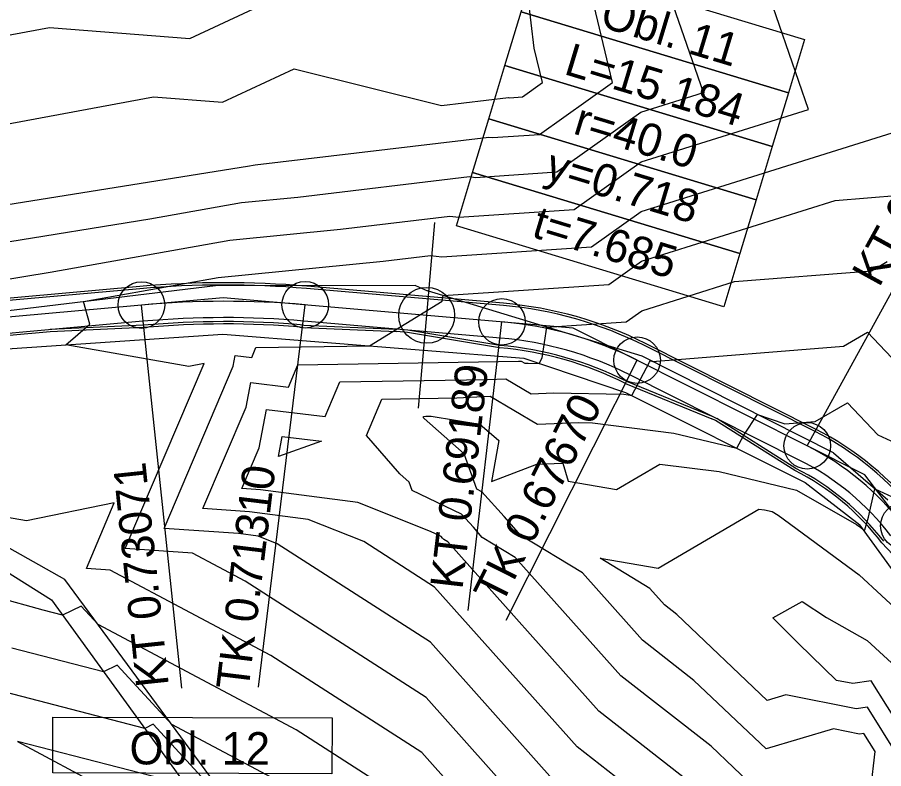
# Model space of a CAD drawing. Extents: x -549394 to -546608, y -1037055 to -1033629.
# Drawn here: x -548286 to -548193, y -1035592.8 to -1035512.1 of the extents above; entities that cross this region are included whole.
import ezdxf

# ---------------------------------------------------------------- set-up
doc = ezdxf.new("R2010")
doc.units = 0
for name, color, linetype in [('hlavni_vrst', 7, 'Continuous'), ('hrana_L', 7, 'Continuous'), ('norm_vrst', 7, 'Continuous'), ('POLYGONY_SITUACE_PO', 7, 'Continuous'), ('u_sirka_1_0m', 7, 'Continuous'), ('x_navrh_C11', 7, 'Continuous'), ('x_osa_C11', 7, 'Continuous'), ('x_popis_oblouky_C11', 7, 'Continuous'), ('x_popis_pricne_rezy_C11', 7, 'Continuous')]:
    doc.layers.add(name, color=color, linetype=linetype)

msp = doc.modelspace()

# ---------------------------------------------------------------- linework, layer by layer
at = {"layer": 'hlavni_vrst'}
for p, q in [((-548212.331, -1035520.205), (-548218.723, -1035501.7)), ((-548219.074, -1035522.316), (-548212.331, -1035520.205)), ((-548228.079, -1035528.712), (-548219.074, -1035522.316)), ((-548236.814, -1035529.301), (-548228.079, -1035528.712)), ((-548255.908, -1035531.413), (-548237.487, -1035529.22)), ((-548237.487, -1035529.22), (-548236.814, -1035529.301)), ((-548261.972, -1035532.012), (-548255.908, -1035531.413)), ((-548271.803, -1035533.774), (-548261.972, -1035532.012)), ((-548298.044, -1035537.991), (-548271.803, -1035533.774)), ((-548197.301, -1035547.423), (-548194.73, -1035545.927)), ((-548194.73, -1035545.927), (-548186.887, -1035554.18)), ((-548217.804, -1035549.058), (-548197.301, -1035547.423)), ((-548220.033, -1035552.739), (-548218.13, -1035549.147)), ((-548218.13, -1035549.147), (-548218.021, -1035548.983)), ((-548218.021, -1035548.983), (-548217.804, -1035549.058)), ((-548252.974, -1035554.992), (-548251.403, -1035551.276)), ((-548251.403, -1035551.276), (-548235.529, -1035551.017)), ((-548235.529, -1035551.017), (-548233.588, -1035550.923)), ((-548233.588, -1035550.923), (-548230.844, -1035552.535)), ((-548230.844, -1035552.535), (-548228.46, -1035552.448)), ((-548228.46, -1035552.448), (-548220.912, -1035552.585)), ((-548220.912, -1035552.585), (-548220.417, -1035552.647)), ((-548220.417, -1035552.647), (-548220.033, -1035552.739)), ((-548260.067, -1035558.338), (-548259.276, -1035554.216)), ((-548259.276, -1035554.216), (-548252.974, -1035554.992)), ((-548261.928, -1035562.711), (-548260.067, -1035558.338)), ((-548259.924, -1035562.848), (-548261.928, -1035562.711)), ((-548249.471, -1035564.211), (-548259.924, -1035562.848)), ((-548241.665, -1035567.316), (-548249.471, -1035564.211)), ((-548240.523, -1035567.864), (-548241.665, -1035567.316)), ((-548240.366, -1035568.038), (-548240.523, -1035567.864)), ((-548240.249, -1035568.171), (-548240.366, -1035568.038)), ((-548239.817, -1035568.434), (-548240.249, -1035568.171)), ((-548223.569, -1035586.629), (-548239.817, -1035568.434)), ((-548283.285, -1035575.769), (-548289.508, -1035574.054)), ((-548279.19, -1035575.353), (-548281.189, -1035576.311)), ((-548277.366, -1035577.326), (-548279.19, -1035575.353)), ((-548281.189, -1035576.311), (-548283.285, -1035575.769)), ((-548256.095, -1035588.612), (-548277.366, -1035577.326)), ((-548209.69, -1035597.452), (-548223.569, -1035586.629)), ((-548243.032, -1035597.002), (-548256.095, -1035588.612))]:
    msp.add_line(p, q, dxfattribs=at)
at = {"layer": 'hrana_L'}
for p, q in [((-548264.75, -1035540.94), (-548291.18, -1035544.12)), ((-548243.27, -1035540.92), (-548264.75, -1035540.94)), ((-548243.27, -1035540.92), (-548241.98, -1035541.48)), ((-548218.94, -1035548.52), (-548241.98, -1035541.48)), ((-548291.26, -1035548), (-548263.97, -1035546.13)), ((-548263.97, -1035546.13), (-548231.65, -1035548.71)), ((-548198.38, -1035558.89), (-548218.94, -1035548.52)), ((-548231.65, -1035548.71), (-548220.71, -1035552.4)), ((-548220.71, -1035552.4), (-548201.42, -1035562.07)), ((-548198.38, -1035558.89), (-548192.54, -1035563.93)), ((-548201.42, -1035562.07), (-548195.55, -1035566.63)), ((-548177.72, -1035591.18), (-548195.55, -1035566.63)), ((-548280.93, -1035572.5), (-548287.66, -1035568.68)), ((-548288.7, -1035570.68), (-548282.38, -1035574.67)), ((-548244.89, -1035621.3), (-548280.93, -1035572.5)), ((-548282.38, -1035574.67), (-548265, -1035598.62))]:
    msp.add_line(p, q, dxfattribs=at)
at = {"layer": 'norm_vrst'}
for p, q in [((-548230.521, -1035515.424), (-548233.103, -1035494.044)), ((-548222.103, -1035519.122), (-548225.312, -1035505.67)), ((-548201.065, -1035522.013), (-548206.946, -1035504.991)), ((-548267.515, -1035514.384), (-548251.739, -1035507.018)), ((-548298.777, -1035516.185), (-548282.595, -1035513.201)), ((-548282.595, -1035513.201), (-548267.515, -1035514.384)), ((-548229.637, -1035519.128), (-548230.521, -1035515.424)), ((-548264.023, -1035521.244), (-548256.296, -1035517.637)), ((-548256.296, -1035517.637), (-548240.489, -1035521.597)), ((-548231.794, -1035520.66), (-548229.637, -1035519.128)), ((-548229.937, -1035524.686), (-548222.103, -1035519.122)), ((-548300.964, -1035526.115), (-548271.409, -1035520.665)), ((-548271.409, -1035520.665), (-548264.023, -1035521.244)), ((-548240.489, -1035521.597), (-548233.296, -1035520.741)), ((-548233.296, -1035520.741), (-548233.189, -1035520.754)), ((-548233.189, -1035520.754), (-548231.794, -1035520.66)), ((-548219.047, -1035527.642), (-548201.065, -1035522.013)), ((-548219.019, -1035532.968), (-548189.799, -1035523.821)), ((-548260.487, -1035527.968), (-548235.392, -1035524.98)), ((-548235.392, -1035524.98), (-548235.001, -1035525.027)), ((-548235.001, -1035525.027), (-548229.937, -1035524.686)), ((-548301.836, -1035534.605), (-548261.098, -1035528.059)), ((-548261.098, -1035528.059), (-548260.72, -1035527.991)), ((-548260.72, -1035527.991), (-548260.487, -1035527.968)), ((-548226.222, -1035532.738), (-548219.047, -1035527.642)), ((-548218.992, -1035538.294), (-548198.182, -1035531.78)), ((-548198.182, -1035531.78), (-548191.252, -1035531.227)), ((-548238.627, -1035533.574), (-548226.222, -1035532.738)), ((-548251.329, -1035534.857), (-548239.582, -1035533.459)), ((-548239.582, -1035533.459), (-548238.627, -1035533.574)), ((-548224.364, -1035536.764), (-548219.019, -1035532.968)), ((-548263.223, -1035536.034), (-548251.329, -1035534.857)), ((-548282.509, -1035539.49), (-548263.223, -1035536.034)), ((-548240.439, -1035537.848), (-548224.364, -1035536.764)), ((-548264.475, -1035540.055), (-548246.75, -1035538.302)), ((-548246.75, -1035538.302), (-548241.678, -1035537.698)), ((-548241.678, -1035537.698), (-548240.439, -1035537.848)), ((-548222.506, -1035540.79), (-548218.992, -1035538.294)), ((-548194.276, -1035539.325), (-548192.595, -1035538.347)), ((-548208.994, -1035540.499), (-548194.276, -1035539.325)), ((-548294.252, -1035541.377), (-548282.509, -1035539.49)), ((-548278.932, -1035542.646), (-548264.475, -1035540.055)), ((-548240.31, -1035541.99), (-548222.506, -1035540.79)), ((-548218.965, -1035543.62), (-548208.994, -1035540.499)), ((-548240.399, -1035542.587), (-548240.31, -1035541.99)), ((-548278.255, -1035545.075), (-548278.932, -1035542.646)), ((-548248.209, -1035547.388), (-548240.399, -1035542.587)), ((-548220.649, -1035544.816), (-548218.965, -1035543.62)), ((-548229.18, -1035545.391), (-548220.649, -1035544.816)), ((-548280.826, -1035547.285), (-548278.255, -1035545.075)), ((-548229.668, -1035548.68), (-548229.18, -1035545.391)), ((-548267.628, -1035549.612), (-548280.826, -1035547.285)), ((-548260.856, -1035548.639), (-548260.412, -1035547.587)), ((-548260.412, -1035547.587), (-548248.209, -1035547.388)), ((-548262.865, -1035549.587), (-548262.641, -1035548.42)), ((-548262.641, -1035548.42), (-548260.856, -1035548.639)), ((-548274.457, -1035569.165), (-548265.994, -1035549.276)), ((-548270.281, -1035567.014), (-548262.865, -1035549.587)), ((-548265.994, -1035549.276), (-548267.628, -1035549.612)), ((-548256.915, -1035551.816), (-548255.908, -1035549.431)), ((-548255.908, -1035549.431), (-548232.214, -1035549.045)), ((-548232.214, -1035549.045), (-548231.932, -1035549.031)), ((-548231.932, -1035549.031), (-548231.533, -1035549.266)), ((-548231.533, -1035549.266), (-548231.187, -1035549.253)), ((-548231.187, -1035549.253), (-548229.975, -1035549.275)), ((-548229.975, -1035549.275), (-548229.668, -1035548.68)), ((-548261.466, -1035553.963), (-548260.959, -1035551.318)), ((-548260.959, -1035551.318), (-548256.915, -1035551.816)), ((-548248.555, -1035557.039), (-548246.899, -1035553.12)), ((-548246.899, -1035553.12), (-548238.845, -1035552.989)), ((-548238.845, -1035552.989), (-548235.245, -1035552.814)), ((-548235.245, -1035552.814), (-548230.155, -1035555.804)), ((-548266.104, -1035564.863), (-548261.466, -1035553.963)), ((-548200.325, -1035555.521), (-548196.864, -1035553.508)), ((-548196.864, -1035553.508), (-548193.608, -1035556.934)), ((-548242.443, -1035555.079), (-548242.395, -1035554.965)), ((-548242.339, -1035555.198), (-548242.443, -1035555.079)), ((-548242.395, -1035554.965), (-548242.161, -1035554.961)), ((-548242.161, -1035554.961), (-548241.598, -1035554.933)), ((-548241.598, -1035554.933), (-548236.356, -1035555.798)), ((-548208.003, -1035556.979), (-548206.535, -1035554.777)), ((-548206.535, -1035554.777), (-548203.599, -1035555.782)), ((-548238.064, -1035558.99), (-548242.339, -1035555.198)), ((-548236.356, -1035555.798), (-548234.32, -1035557.548)), ((-548230.155, -1035555.804), (-548225.734, -1035555.643)), ((-548225.734, -1035555.643), (-548224.273, -1035555.67)), ((-548224.273, -1035555.67), (-548215.537, -1035556.764)), ((-548203.599, -1035555.782), (-548200.325, -1035555.521)), ((-548244.966, -1035561.123), (-548248.555, -1035557.039)), ((-548215.537, -1035556.764), (-548208.752, -1035558.394)), ((-548208.752, -1035558.394), (-548208.003, -1035556.979)), ((-548193.608, -1035556.934), (-548186.719, -1035560.212)), ((-548258.007, -1035559.267), (-548257.594, -1035557.114)), ((-548253.387, -1035557.633), (-548258.007, -1035559.267)), ((-548257.594, -1035557.114), (-548253.387, -1035557.633)), ((-548234.32, -1035557.548), (-548235.097, -1035561.951)), ((-548236.702, -1035562.795), (-548238.064, -1035558.99)), ((-548235.097, -1035561.951), (-548230.229, -1035560.105)), ((-548230.229, -1035560.105), (-548227.447, -1035559.983)), ((-548227.447, -1035559.983), (-548226.871, -1035561.932)), ((-548221.686, -1035562.83), (-548217.017, -1035560.084)), ((-548217.017, -1035560.084), (-548210.657, -1035560.88)), ((-548243.954, -1035562.021), (-548244.966, -1035561.123)), ((-548210.657, -1035560.88), (-548202.336, -1035562.88)), ((-548243.632, -1035562.921), (-548243.954, -1035562.021)), ((-548226.871, -1035561.932), (-548221.686, -1035562.83)), ((-548238.328, -1035565.466), (-548243.632, -1035562.921)), ((-548236.133, -1035563.068), (-548236.702, -1035562.795)), ((-548233.745, -1035565.724), (-548236.133, -1035563.068)), ((-548202.336, -1035562.88), (-548195.887, -1035566.589)), ((-548194.624, -1035565.799), (-548193.923, -1035562.736)), ((-548193.923, -1035562.736), (-548192.059, -1035563.623)), ((-548275.63, -1035564.259), (-548285.047, -1035566.193)), ((-548278.633, -1035571.317), (-548275.63, -1035564.259)), ((-548261.11, -1035565.203), (-548266.104, -1035564.863)), ((-548254.822, -1035566.023), (-548261.11, -1035565.203)), ((-548217.219, -1035571.277), (-548206.407, -1035564.918)), ((-548206.407, -1035564.918), (-548205.777, -1035564.997)), ((-548205.777, -1035564.997), (-548204.952, -1035565.195)), ((-548204.952, -1035565.195), (-548204.313, -1035565.563)), ((-548285.047, -1035566.193), (-548288.189, -1035565.639)), ((-548248.839, -1035568.403), (-548254.822, -1035566.023)), ((-548237.056, -1035566.881), (-548238.328, -1035565.466)), ((-548231.948, -1035567.76), (-548233.745, -1035565.724)), ((-548204.313, -1035565.563), (-548195.599, -1035571.992)), ((-548194.999, -1035567.161), (-548194.624, -1035565.799)), ((-548262.295, -1035567.559), (-548270.281, -1035567.014)), ((-548236.098, -1035567.966), (-548237.056, -1035566.881)), ((-548195.887, -1035566.589), (-548195.552, -1035566.836)), ((-548195.552, -1035566.836), (-548195.087, -1035567.268)), ((-548195.087, -1035567.268), (-548194.999, -1035567.161)), ((-548260.172, -1035567.836), (-548262.295, -1035567.559)), ((-548258.151, -1035568.639), (-548260.172, -1035567.836)), ((-548232.58, -1035570.104), (-548236.098, -1035567.966)), ((-548225.343, -1035571.775), (-548231.948, -1035567.76)), ((-548241.673, -1035579.223), (-548258.151, -1035568.639)), ((-548241.22, -1035573.297), (-548248.839, -1035568.403)), ((-548267.231, -1035569.658), (-548274.457, -1035569.165)), ((-548261.561, -1035572.667), (-548267.231, -1035569.658)), ((-548221.226, -1035582.819), (-548232.58, -1035570.104)), ((-548223.446, -1035570.199), (-548217.219, -1035571.277)), ((-548218.106, -1035573.445), (-548223.446, -1035570.199)), ((-548276.069, -1035571.492), (-548278.633, -1035571.317)), ((-548258.828, -1035580.639), (-548276.069, -1035571.492)), ((-548218.883, -1035579.009), (-548225.343, -1035571.775)), ((-548242.126, -1035585.149), (-548261.561, -1035572.667)), ((-548195.599, -1035571.992), (-548183.509, -1035583.209)), ((-548225.912, -1035590.439), (-548241.22, -1035573.297)), ((-548216.54, -1035575.199), (-548218.106, -1035573.445)), ((-548215.202, -1035576.242), (-548216.54, -1035575.199)), ((-548204.896, -1035576.606), (-548201.75, -1035574.861)), ((-548201.75, -1035574.861), (-548199.11, -1035576.548)), ((-548205.485, -1035585.462), (-548215.202, -1035576.242)), ((-548199.11, -1035576.548), (-548194.75, -1035579.044)), ((-548202.122, -1035579.344), (-548204.896, -1035576.606)), ((-548228.255, -1035594.249), (-548241.673, -1035579.223)), ((-548213.365, -1035583.312), (-548218.883, -1035579.009)), ((-548198.033, -1035583.317), (-548202.122, -1035579.344)), ((-548194.75, -1035579.044), (-548187.061, -1035586.129)), ((-548276.778, -1035582.39), (-548286.638, -1035579.841)), ((-548242.579, -1035591.076), (-548258.828, -1035580.639)), ((-548275.324, -1035581.693), (-548276.778, -1035582.39)), ((-548269.445, -1035588.052), (-548275.324, -1035581.693)), ((-548211.527, -1035590.382), (-548221.226, -1035582.819)), ((-548272.367, -1035588.469), (-548289.991, -1035583.913)), ((-548205.603, -1035590.677), (-548213.365, -1035583.312)), ((-548196.308, -1035583.659), (-548198.033, -1035583.317)), ((-548194.312, -1035583.363), (-548196.308, -1035583.659)), ((-548189.035, -1035591.853), (-548194.312, -1035583.363)), ((-548203.494, -1035584.869), (-548205.485, -1035585.462)), ((-548195.938, -1035586.37), (-548203.494, -1035584.869)), ((-548230.598, -1035598.059), (-548242.126, -1035585.149)), ((-548194.713, -1035586.188), (-548195.938, -1035586.37)), ((-548191.473, -1035591.4), (-548194.713, -1035586.188)), ((-548271.457, -1035588.033), (-548272.367, -1035588.469)), ((-548261.524, -1035598.777), (-548271.457, -1035588.033)), ((-548253.362, -1035596.585), (-548269.445, -1035588.052)), ((-548198.372, -1035588.524), (-548205.603, -1035590.677)), ((-548195.568, -1035589.081), (-548198.372, -1035588.524)), ((-548195.114, -1035589.013), (-548195.568, -1035589.081)), ((-548193.912, -1035590.947), (-548195.114, -1035589.013)), ((-548286.044, -1035589.872), (-548265.573, -1035600.78)), ((-548267.955, -1035594.547), (-548286.044, -1035589.872)), ((-548207.852, -1035604.522), (-548225.912, -1035590.439)), ((-548205.72, -1035595.892), (-548211.527, -1035590.382)), ((-548232.941, -1035601.869), (-548242.579, -1035591.076)), ((-548195.064, -1035601.284), (-548193.912, -1035590.947))]:
    msp.add_line(p, q, dxfattribs=at)
at = {"layer": 'POLYGONY_SITUACE_PO'}
for centre in [(-548272.716, -1035543.014), (-548255.121, -1035542.985), (-548233.989, -1035544.817), (-548219.469, -1035548.934), (-548201.193, -1035558.128), (-548190.82, -1035566.734)]:
    msp.add_circle(centre, 2.5, dxfattribs=at)
at = {"layer": 'u_sirka_1_0m'}
msp.add_circle((-548242.073, -1035544.116), 3, dxfattribs=at)
at = {"layer": 'x_navrh_C11'}
for p, q in [((-548272.873, -1035541.271), (-548341.255, -1035547.422)), ((-548233.838, -1035543.074), (-548254.97, -1035541.242)), ((-548272.559, -1035544.757), (-548340.941, -1035550.908)), ((-548234.14, -1035546.561), (-548255.272, -1035544.729)), ((-548272.521, -1035545.185), (-548282.519, -1035545.653)), ((-548272.504, -1035545.435), (-548282.502, -1035545.902)), ((-548255.326, -1035545.407), (-548245.326, -1035545.842)), ((-548255.309, -1035545.157), (-548245.31, -1035545.592)), ((-548234.209, -1035547.348), (-548244.103, -1035545.697)), ((-548234.24, -1035547.596), (-548244.135, -1035545.945)), ((-548200.406, -1035556.564), (-548218.682, -1035547.371)), ((-548200.294, -1035556.341), (-548218.57, -1035547.147)), ((-548201.979, -1035559.691), (-548220.255, -1035550.497)), ((-548220.713, -1035551.431), (-548211.425, -1035555.219)), ((-548220.61, -1035551.203), (-548211.322, -1035554.991)), ((-548211.036, -1035555.415), (-548211.425, -1035555.219)), ((-548202.538, -1035560.775), (-548211.036, -1035555.415)), ((-548202.415, -1035560.557), (-548210.912, -1035555.197)), ((-548193.175, -1035568.545), (-548186.339, -1035575.908))]:
    msp.add_line(p, q, dxfattribs=at)
for points in [[(-548272.895, -1035541.022), (-548331.308, -1035546.276)], [(-548233.816, -1035542.825), (-548254.948, -1035540.993)], [(-548244.135, -1035545.945), (-548245.326, -1035545.842)], [(-548282.502, -1035545.902), (-548340.919, -1035551.157)]]:
    msp.add_lwpolyline(points, dxfattribs=at)
for centre, radius, start, end in [((-548263.757, -1035642.612), 102, 85.04573, 95.1399), ((-548263.757, -1035642.612), 101.75, 85.04573, 95.1399), ((-548237.444, -1035584.668), 41.75, 63.29598, 85.04573), ((-548237.444, -1035584.668), 42, 63.29598, 85.04573), ((-548263.757, -1035642.612), 98.25, 85.04573, 95.1399), ((-548263.757, -1035642.612), 97.82, 85.04573, 95.1399), ((-548263.757, -1035642.612), 97.57, 85.04258, 95.14305), ((-548237.444, -1035584.668), 38.25, 63.29598, 85.04573), ((-548237.444, -1035584.668), 37.21, 63.28083, 85.06089), ((-548237.444, -1035584.668), 37.46, 63.29598, 85.04573), ((-548214.674, -1035584.928), 31.75, 37.33324, 63.29598), ((-548214.674, -1035584.928), 32, 37.33324, 63.29598), ((-548214.674, -1035584.928), 28.25, 37.33324, 63.29598), ((-548214.674, -1035584.928), 27.03, 37.30766, 63.32157), ((-548214.674, -1035584.928), 27.28, 37.33324, 63.29598)]:
    msp.add_arc(centre, radius, start, end, dxfattribs=at)
at = {"layer": 'x_osa_C11'}
for points in [[(-548226.333, -1035545.481), (-548263.92, -1035542.223), (-548352.411, -1035550.182)], [(-548195.015, -1035561.235), (-548226.333, -1035545.481)], [(-548155.025, -1035618.245), (-548174.113, -1035588.64), (-548195.015, -1035561.235)]]:
    msp.add_lwpolyline(points, dxfattribs=at)
for centre, radius, start, end in [((-548263.757, -1035642.612), 100, 85.04573, 95.1399), ((-548237.444, -1035584.668), 40, 63.29598, 85.04573), ((-548214.674, -1035584.928), 30, 37.33324, 63.29598)]:
    msp.add_arc(centre, radius, start, end, dxfattribs=at)
at = {"layer": 'x_popis_oblouky_C11'}
for points in [[(-548230.188, -1035505.8), (-548201.475, -1035514.493), (-548203.214, -1035520.235), (-548231.927, -1035511.542)], [(-548231.927, -1035511.542), (-548203.214, -1035520.235), (-548204.953, -1035525.978), (-548233.665, -1035517.285)], [(-548233.665, -1035517.285), (-548204.953, -1035525.978), (-548206.691, -1035531.721), (-548235.404, -1035523.028)], [(-548235.404, -1035523.028), (-548206.691, -1035531.721), (-548208.43, -1035537.463), (-548237.143, -1035528.77)], [(-548237.143, -1035528.77), (-548208.43, -1035537.463), (-548210.168, -1035543.206), (-548238.881, -1035534.513)], [(-548282.226, -1035587.248), (-548252.226, -1035587.353), (-548252.247, -1035593.353), (-548282.247, -1035593.248)]]:
    msp.add_lwpolyline(points, close=True, dxfattribs=at)
for points in [[(-548201.184, -1035558.129), (-548181.242, -1035521.879)], [(-548268.386, -1035584.16), (-548272.716, -1035543.014)], [(-548260.129, -1035584.054), (-548255.121, -1035542.985)], [(-548237.607, -1035575.829), (-548233.989, -1035544.817)], [(-548233.52, -1035576.838), (-548219.469, -1035548.934)]]:
    msp.add_lwpolyline(points, dxfattribs=at)
at = {"layer": 'x_popis_pricne_rezy_C11'}
msp.add_lwpolyline([(-548242.936, -1035554.079), (-548242.073, -1035544.116), (-548241.209, -1035534.154)], dxfattribs=at)

# ---------------------------------------------------------------- texts
at = {"layer": 'x_popis_oblouky_C11'}
for s, rotation, p in [('Obl. 11', 343.17807, (-548223.611, -1035513.072)), ('L=15.184', 343.17807, (-548227.452, -1035518.179)), ('KT 0.65624', 61.18274, (-548193.476, -1035541.217)), ('r=40.0', 343.17807, (-548226.463, -1035524.567)), ('y=0.718', 343.17807, (-548229.525, -1035529.448)), ('t=7.685', 343.17807, (-548230.919, -1035535.663)), ('KT 0.69189', 83.34646, (-548238.24, -1035573.619)), ('TK 0.67670', 63.27133, (-548234.037, -1035575.341)), ('KT 0.73071', 96.00699, (-548269.768, -1035583.842)), ('TK 0.71310', 83.04818, (-548261.226, -1035584.467)), ('Obl. 12', 359.82224, (-548273.997, -1035592.332))]:
    msp.add_text(s, height=3.5, rotation=rotation, dxfattribs=at).set_placement(p)

doc.saveas('drawing.dxf')
